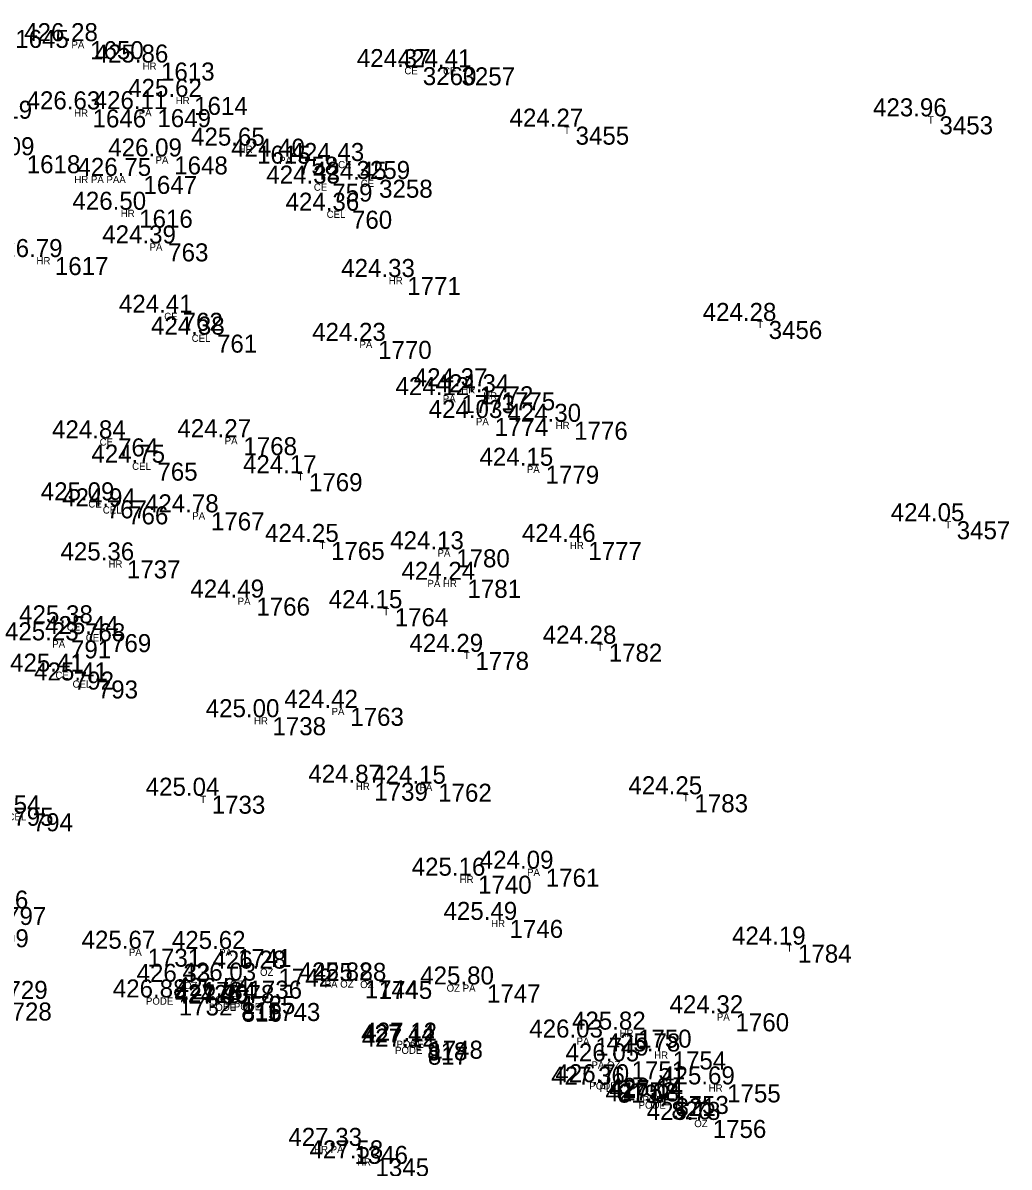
# Model space of a CAD drawing. Extents: x -639390 to -639075, y -1138747 to -1138358.
# Drawn here: x -639243.09 to -639202.03, y -1138603.62 to -1138555.98 of the extents above; entities that cross this region are included whole.
import ezdxf

# ---------------------------------------------------------------- set-up
doc = ezdxf.new("R2010")
doc.units = 0
for name, color, linetype in [('Vrstva 11', 7, 'Continuous'), ('Vrstva 12', 7, 'Continuous'), ('Vrstva 13', 7, 'Continuous'), ('Vrstva 57', 7, 'Continuous')]:
    doc.layers.add(name, color=color, linetype=linetype)

msp = doc.modelspace()

# ---------------------------------------------------------------- linework, layer by layer
at = {"layer": 'Vrstva 11'}
for p, q in [((-639240.57, -1138556.74), (-639240.57, -1138556.74)), ((-639237.62, -1138557.63), (-639237.62, -1138557.63)), ((-639226.72, -1138557.82), (-639226.72, -1138557.82)), ((-639225.11, -1138557.83), (-639225.11, -1138557.83)), ((-639236.24, -1138559.06), (-639236.24, -1138559.06)), ((-639240.47, -1138559.58), (-639240.47, -1138559.58)), ((-639237.77, -1138559.57), (-639237.77, -1138559.57)), ((-639205.21, -1138559.87), (-639205.21, -1138559.87)), ((-639220.36, -1138560.3), (-639220.36, -1138560.3)), ((-639233.62, -1138561.09), (-639233.62, -1138561.09)), ((-639237.07, -1138561.54), (-639237.07, -1138561.54)), ((-639231.92, -1138561.55), (-639231.92, -1138561.55)), ((-639229.48, -1138561.73), (-639229.48, -1138561.73)), ((-639238.35, -1138562.35), (-639238.35, -1138562.35)), ((-639230.49, -1138562.67), (-639230.49, -1138562.67)), ((-639228.54, -1138562.51), (-639228.54, -1138562.51)), ((-639238.53, -1138563.76), (-639238.53, -1138563.76)), ((-639229.67, -1138563.8), (-639229.67, -1138563.8)), ((-639237.32, -1138565.16), (-639237.32, -1138565.16)), ((-639242.04, -1138565.73), (-639242.04, -1138565.73)), ((-639227.37, -1138566.56), (-639227.37, -1138566.56)), ((-639236.72, -1138568.05), (-639236.72, -1138568.05)), ((-639212.32, -1138568.39), (-639212.32, -1138568.39)), ((-639235.29, -1138568.96), (-639235.29, -1138568.96)), ((-639228.58, -1138569.22), (-639228.58, -1138569.22)), ((-639224.35, -1138571.11), (-639224.35, -1138571.11)), ((-639223.44, -1138571.36), (-639223.44, -1138571.36)), ((-639225.11, -1138571.48), (-639225.11, -1138571.48)), ((-639223.73, -1138572.43), (-639223.73, -1138572.43)), ((-639220.42, -1138572.59), (-639220.42, -1138572.59)), ((-639239.41, -1138573.28), (-639239.41, -1138573.28)), ((-639234.19, -1138573.23), (-639234.19, -1138573.23)), ((-639237.77, -1138574.29), (-639237.77, -1138574.29)), ((-639231.46, -1138574.73), (-639231.46, -1138574.73)), ((-639221.61, -1138574.42), (-639221.61, -1138574.42)), ((-639239.88, -1138575.86), (-639239.88, -1138575.86)), ((-639238.99, -1138576.11), (-639238.99, -1138576.11)), ((-639235.54, -1138576.36), (-639235.54, -1138576.36)), ((-639204.49, -1138576.73), (-639204.49, -1138576.73)), ((-639230.54, -1138577.59), (-639230.54, -1138577.59)), ((-639225.33, -1138577.9), (-639225.33, -1138577.9)), ((-639219.83, -1138577.59), (-639219.83, -1138577.59)), ((-639239.04, -1138578.36), (-639239.04, -1138578.36)), ((-639224.86, -1138579.17), (-639224.86, -1138579.17)), ((-639233.65, -1138579.91), (-639233.65, -1138579.91)), ((-639227.89, -1138580.35), (-639227.89, -1138580.35)), ((-639240.78, -1138580.98), (-639240.78, -1138580.98)), ((-639241.37, -1138581.69), (-639241.37, -1138581.69)), ((-639239.7, -1138581.43), (-639239.7, -1138581.43)), ((-639218.98, -1138581.83), (-639218.98, -1138581.83)), ((-639224.53, -1138582.17), (-639224.53, -1138582.17)), ((-639241.25, -1138582.99), (-639241.25, -1138582.99)), ((-639240.25, -1138583.36), (-639240.25, -1138583.36)), ((-639229.74, -1138584.5), (-639229.74, -1138584.5)), ((-639232.98, -1138584.89), (-639232.98, -1138584.89)), ((-639228.74, -1138587.62), (-639228.74, -1138587.62)), ((-639226.08, -1138587.66), (-639226.08, -1138587.66)), ((-639235.51, -1138588.16), (-639235.51, -1138588.16)), ((-639215.41, -1138588.1), (-639215.41, -1138588.1)), ((-639242.96, -1138588.89), (-639242.96, -1138588.89)), ((-639221.6, -1138591.2), (-639221.6, -1138591.2)), ((-639224.42, -1138591.49), (-639224.42, -1138591.49)), ((-639223.11, -1138593.33), (-639223.11, -1138593.33)), ((-639238.18, -1138594.53), (-639238.18, -1138594.53)), ((-639234.42, -1138594.54), (-639234.42, -1138594.54)), ((-639211.1, -1138594.36), (-639211.1, -1138594.36)), ((-639232.73, -1138595.36), (-639232.73, -1138595.36)), ((-639235.89, -1138595.91), (-639235.89, -1138595.91)), ((-639233.98, -1138595.86), (-639233.98, -1138595.86)), ((-639229.14, -1138595.85), (-639229.14, -1138595.85)), ((-639228.56, -1138595.87), (-639228.56, -1138595.87)), ((-639224.05, -1138596.02), (-639224.05, -1138596.02)), ((-639236.88, -1138596.56), (-639236.88, -1138596.56)), ((-639234.26, -1138596.5), (-639234.26, -1138596.5)), ((-639234.28, -1138596.76), (-639234.28, -1138596.76)), ((-639234.26, -1138596.82), (-639234.26, -1138596.82)), ((-639233.22, -1138596.79), (-639233.22, -1138596.79)), ((-639213.7, -1138597.22), (-639213.7, -1138597.22)), ((-639217.76, -1138597.9), (-639217.76, -1138597.9)), ((-639226.54, -1138598.43), (-639226.54, -1138598.43)), ((-639226.45, -1138598.36), (-639226.45, -1138598.36)), ((-639219.54, -1138598.23), (-639219.54, -1138598.23)), ((-639226.51, -1138598.61), (-639226.51, -1138598.61)), ((-639216.32, -1138598.81), (-639216.32, -1138598.81)), ((-639218.03, -1138599.22), (-639218.03, -1138599.22)), ((-639218.61, -1138600.19), (-639218.61, -1138600.19)), ((-639218.42, -1138600.09), (-639218.42, -1138600.09)), ((-639214.05, -1138600.18), (-639214.05, -1138600.18)), ((-639216.37, -1138600.89), (-639216.37, -1138600.89)), ((-639216.21, -1138600.66), (-639216.21, -1138600.66)), ((-639216.2, -1138600.75), (-639216.2, -1138600.75)), ((-639214.65, -1138601.66), (-639214.65, -1138601.66)), ((-639229.57, -1138602.74), (-639229.57, -1138602.74)), ((-639228.69, -1138603.26), (-639228.69, -1138603.26))]:
    msp.add_line(p, q, dxfattribs=at)

# ---------------------------------------------------------------- texts
at = {"layer": 'Vrstva 12'}
for s, p in [('426.28 ', (-639243.039, -1138556.74)), ('425.86 ', (-639240.106, -1138557.63)), ('424.37 ', (-639229.189, -1138557.82)), ('424.41 ', (-639227.485, -1138557.83)), ('425.62 ', (-639238.709, -1138559.06)), ('426.63 ', (-639242.939, -1138559.58)), ('426.11 ', (-639240.145, -1138559.57)), ('423.96 ', (-639207.696, -1138559.87)), ('424.27 ', (-639222.829, -1138560.3)), ('425.65 ', (-639236.09, -1138561.09)), ('427.09 ', (-639245.679, -1138561.49)), ('426.09 ', (-639239.539, -1138561.54)), ('424.40 ', (-639234.419, -1138561.55)), ('424.43 ', (-639231.949, -1138561.73)), ('426.75 ', (-639240.82, -1138562.35)), ('424.45 ', (-639231.01, -1138562.51)), ('424.33 ', (-639232.959, -1138562.67)), ('426.50 ', (-639241.029, -1138563.76)), ('424.36 ', (-639232.156, -1138563.8)), ('424.39 ', (-639239.789, -1138565.16)), ('426.79 ', (-639244.509, -1138565.73)), ('424.33 ', (-639229.839, -1138566.56)), ('424.41 ', (-639239.095, -1138568.05)), ('424.28 ', (-639214.789, -1138568.39)), ('424.38 ', (-639237.759, -1138568.96)), ('424.23 ', (-639231.049, -1138569.22)), ('424.37 ', (-639226.819, -1138571.11)), ('424.12 ', (-639227.579, -1138571.48)), ('424.34 ', (-639225.909, -1138571.36)), ('424.03 ', (-639226.199, -1138572.43)), ('424.30 ', (-639222.919, -1138572.59)), ('424.84 ', (-639241.879, -1138573.28)), ('424.27 ', (-639236.659, -1138573.23)), ('424.75 ', (-639240.24, -1138574.29)), ('424.15 ', (-639224.08, -1138574.42)), ('424.17 ', (-639233.929, -1138574.73)), ('425.09 ', (-639242.349, -1138575.86)), ('424.94 ', (-639241.459, -1138576.11)), ('424.78 ', (-639238.009, -1138576.36)), ('424.05 ', (-639206.96, -1138576.73)), ('424.25 ', (-639233.01, -1138577.59)), ('424.46 ', (-639222.316, -1138577.59)), ('424.13 ', (-639227.799, -1138577.9)), ('425.36 ', (-639241.526, -1138578.36)), ('424.24 ', (-639227.329, -1138579.17)), ('424.49 ', (-639236.119, -1138579.91)), ('424.15 ', (-639230.36, -1138580.35)), ('425.38 ', (-639243.249, -1138580.98)), ('425.44 ', (-639242.169, -1138581.43)), ('425.23 ', (-639243.839, -1138581.69)), ('424.28 ', (-639221.449, -1138581.83)), ('424.29 ', (-639226.999, -1138582.17)), ('425.41 ', (-639243.625, -1138582.99)), ('425.41 ', (-639242.625, -1138583.36)), ('424.42 ', (-639232.209, -1138584.5)), ('425.00 ', (-639235.479, -1138584.89)), ('424.87 ', (-639231.209, -1138587.62)), ('424.15 ', (-639228.55, -1138587.66)), ('425.04 ', (-639237.979, -1138588.16)), ('424.25 ', (-639217.88, -1138588.1)), ('425.54 ', (-639245.429, -1138588.89)), ('424.09 ', (-639224.069, -1138591.2)), ('425.16 ', (-639226.906, -1138591.49)), ('425.49 ', (-639225.579, -1138593.33)), ('425.67 ', (-639240.649, -1138594.53)), ('425.62 ', (-639236.889, -1138594.54)), ('424.19 ', (-639213.569, -1138594.36)), ('426.28 ', (-639235.199, -1138595.36)), ('426.33 ', (-639238.359, -1138595.91)), ('426.03 ', (-639236.449, -1138595.86)), ('425.82 ', (-639231.609, -1138595.85)), ('425.88 ', (-639231.029, -1138595.87)), ('425.80 ', (-639226.549, -1138596.02)), ('426.88 ', (-639239.349, -1138596.56)), ('427.40 ', (-639236.779, -1138596.76)), ('427.30 ', (-639236.759, -1138596.82)), ('426.64 ', (-639236.729, -1138596.5)), ('426.78 ', (-639235.689, -1138596.79)), ('424.32 ', (-639216.169, -1138597.22)), ('427.12 ', (-639228.919, -1138598.36)), ('426.03 ', (-639222.009, -1138598.23)), ('425.82 ', (-639220.229, -1138597.9)), ('427.44 ', (-639229.009, -1138598.43)), ('427.12 ', (-639228.979, -1138598.61)), ('425.78 ', (-639218.789, -1138598.81)), ('426.05 ', (-639220.5, -1138599.22)), ('427.36 ', (-639221.096, -1138600.19)), ('426.70 ', (-639220.919, -1138600.09)), ('425.69 ', (-639216.519, -1138600.18)), ('426.64 ', (-639218.679, -1138600.66)), ('427.08 ', (-639218.839, -1138600.89)), ('427.14 ', (-639218.669, -1138600.75)), ('425.78 ', (-639217.119, -1138601.66)), ('427.33 ', (-639232.039, -1138602.74)), ('427.58 ', (-639231.159, -1138603.26))]:
    msp.add_text(s, height=0.75, dxfattribs=at).set_placement(p)
at = {"layer": 'Vrstva 13'}
for s, p in [(' 1645', (-639243.69, -1138557.02)), (' 1650', (-639240.57, -1138557.49)), (' 1613', (-639237.62, -1138558.38)), (' 3260', (-639226.72, -1138558.57)), (' 3257', (-639225.11, -1138558.58)), (' 1619', (-639245.22, -1138559.97)), (' 1614', (-639236.24, -1138559.81)), (' 1646', (-639240.47, -1138560.33)), (' 1649', (-639237.77, -1138560.32)), (' 3453', (-639205.21, -1138560.62)), (' 3455', (-639220.36, -1138561.05)), (' 1615', (-639233.62, -1138561.84)), (' 1618', (-639243.21, -1138562.24)), (' 1648', (-639237.07, -1138562.29)), (' 758', (-639231.92, -1138562.3)), (' 3259', (-639229.48, -1138562.48)), (' 1647', (-639238.35, -1138563.1)), (' 759', (-639230.49, -1138563.42)), (' 3258', (-639228.54, -1138563.26)), (' 1616', (-639238.53, -1138564.51)), (' 760', (-639229.67, -1138564.55)), (' 763', (-639237.32, -1138565.91)), (' 1617', (-639242.04, -1138566.48)), (' 1771', (-639227.37, -1138567.31)), (' 762', (-639236.72, -1138568.8)), (' 3456', (-639212.32, -1138569.14)), (' 761', (-639235.29, -1138569.71)), (' 1770', (-639228.58, -1138569.97)), (' 1772', (-639224.35, -1138571.86)), (' 1775', (-639223.44, -1138572.11)), (' 1773', (-639225.11, -1138572.23)), (' 1774', (-639223.73, -1138573.18)), (' 1776', (-639220.42, -1138573.34)), (' 764', (-639239.41, -1138574.03)), (' 1768', (-639234.19, -1138573.98)), (' 765', (-639237.77, -1138575.04)), (' 1769', (-639231.46, -1138575.48)), (' 1779', (-639221.61, -1138575.17)), (' 767', (-639239.88, -1138576.61)), (' 766', (-639238.99, -1138576.86)), (' 1767', (-639235.54, -1138577.11)), (' 3457', (-639204.49, -1138577.48)), (' 1765', (-639230.54, -1138578.34)), (' 1780', (-639225.33, -1138578.65)), (' 1777', (-639219.83, -1138578.34)), (' 1737', (-639239.04, -1138579.11)), (' 1781', (-639224.86, -1138579.92)), (' 1766', (-639233.65, -1138580.66)), (' 1764', (-639227.89, -1138581.1)), (' 768', (-639240.78, -1138581.73)), (' 791', (-639241.37, -1138582.44)), (' 769', (-639239.7, -1138582.18)), (' 1782', (-639218.98, -1138582.58)), (' 1778', (-639224.53, -1138582.92)), (' 792', (-639241.25, -1138583.74)), (' 793', (-639240.25, -1138584.11)), (' 1763', (-639229.74, -1138585.25)), (' 1738', (-639232.98, -1138585.64)), (' 1739', (-639228.74, -1138588.37)), (' 1762', (-639226.08, -1138588.41)), (' 1733', (-639235.51, -1138588.91)), (' 1783', (-639215.41, -1138588.85)), (' 795', (-639243.77, -1138589.41)), (' 794', (-639242.96, -1138589.64)), (' 1761', (-639221.6, -1138591.95)), (' 1740', (-639224.42, -1138592.24)), (' 796', (-639244.82, -1138592.86)), (' 797', (-639244.07, -1138593.54)), (' 809', (-639244.8, -1138594.47)), (' 1746', (-639223.11, -1138594.08)), (' 1731', (-639238.18, -1138595.28)), (' 1741', (-639234.42, -1138595.29)), (' 1784', (-639211.1, -1138595.11)), (' 1742', (-639232.73, -1138596.11)), (' 1729', (-639244.57, -1138596.62)), (' 1734', (-639235.89, -1138596.66)), (' 1736', (-639233.98, -1138596.61)), (' 1744', (-639229.14, -1138596.6)), (' 1745', (-639228.56, -1138596.62)), (' 1747', (-639224.05, -1138596.77)), (' 1732', (-639236.88, -1138597.31)), (' 1735', (-639234.26, -1138597.25)), (' 1728', (-639244.4, -1138597.52)), (' 815', (-639234.28, -1138597.51)), (' 816', (-639234.26, -1138597.57)), (' 1743', (-639233.22, -1138597.54)), (' 1760', (-639213.7, -1138597.97)), (' 1750', (-639217.76, -1138598.65)), (' 818', (-639226.54, -1138599.18)), (' 1748', (-639226.45, -1138599.11)), (' 1749', (-639219.54, -1138598.98)), (' 817', (-639226.51, -1138599.36)), (' 1754', (-639216.32, -1138599.56)), (' 1751', (-639218.03, -1138599.97)), (' 819', (-639218.61, -1138600.94)), (' 1752', (-639218.42, -1138600.84)), (' 1755', (-639214.05, -1138600.93)), (' 820', (-639216.37, -1138601.64)), (' 821', (-639216.2, -1138601.5)), (' 1753', (-639216.21, -1138601.41)), (' 1756', (-639214.65, -1138602.41)), (' 1346', (-639229.57, -1138603.49)), (' 1345', (-639228.69, -1138604.01))]:
    msp.add_text(s, height=0.75, dxfattribs=at).set_placement(p)
at = {"layer": 'Vrstva 57'}
for s, p in [('PA', (-639241.07, -1138557.04)), ('HR', (-639238.109, -1138557.93)), ('CE', (-639227.208, -1138558.12)), ('CE', (-639225.598, -1138558.13)), ('HR', (-639236.729, -1138559.36)), ('HR', (-639240.959, -1138559.88)), ('PA', (-639238.27, -1138559.87)), ('T', (-639205.41, -1138560.17)), ('T', (-639220.56, -1138560.6)), ('HR', (-639234.109, -1138561.39)), ('PA', (-639237.57, -1138561.84)), ('PA', (-639232.42, -1138561.85)), ('CE', (-639229.968, -1138562.03)), ('HR PA PAA', (-639240.95, -1138562.65)), ('CE', (-639230.978, -1138562.97)), ('CE', (-639229.027, -1138562.81)), ('HR', (-639239.019, -1138564.06)), ('CEL', (-639230.445, -1138564.1)), ('PA', (-639237.82, -1138565.46)), ('HR', (-639242.529, -1138566.03)), ('HR', (-639227.859, -1138566.86)), ('CE', (-639237.208, -1138568.35)), ('T', (-639212.52, -1138568.69)), ('CEL', (-639236.065, -1138569.26)), ('PA', (-639229.08, -1138569.52)), ('HR', (-639224.839, -1138571.41)), ('HR', (-639223.929, -1138571.66)), ('PA', (-639225.61, -1138571.78)), ('PA', (-639224.23, -1138572.73)), ('HR', (-639220.909, -1138572.89)), ('CE', (-639239.897, -1138573.58)), ('PA', (-639234.69, -1138573.53)), ('CEL', (-639238.545, -1138574.59)), ('T', (-639231.66, -1138575.03)), ('PA', (-639222.11, -1138574.72)), ('CE', (-639240.368, -1138576.16)), ('CEL', (-639239.765, -1138576.41)), ('PA', (-639236.04, -1138576.66)), ('T', (-639204.69, -1138577.03)), ('T', (-639230.74, -1138577.89)), ('PA', (-639225.83, -1138578.2)), ('HR', (-639220.319, -1138577.89)), ('HR', (-639239.529, -1138578.66)), ('PA HR', (-639226.249, -1138579.47)), ('PA', (-639234.15, -1138580.21)), ('T', (-639228.09, -1138580.65)), ('CE', (-639241.267, -1138581.28)), ('PA', (-639241.87, -1138581.99)), ('CEL', (-639240.475, -1138581.73)), ('T', (-639219.18, -1138582.13)), ('T', (-639224.73, -1138582.47)), ('CE', (-639241.738, -1138583.29)), ('CEL', (-639241.025, -1138583.66)), ('PA', (-639230.24, -1138584.8)), ('HR', (-639233.469, -1138585.19)), ('HR', (-639229.229, -1138587.92)), ('PA', (-639226.58, -1138587.96)), ('T', (-639235.71, -1138588.46)), ('T', (-639215.61, -1138588.4)), ('CEL', (-639243.735, -1138589.19)), ('PA', (-639222.1, -1138591.5)), ('HR', (-639224.909, -1138591.79)), ('HR', (-639223.599, -1138593.63)), ('PA', (-639238.68, -1138594.83)), ('PA', (-639234.92, -1138594.84)), ('T', (-639211.3, -1138594.66)), ('OZ', (-639233.219, -1138595.66)), ('OZ', (-639236.379, -1138596.21)), ('OZ', (-639234.469, -1138596.16)), ('PA OZ', (-639230.529, -1138596.15)), ('OZ', (-639229.049, -1138596.17)), ('OZ PA', (-639225.45, -1138596.32)), ('PODE', (-639237.968, -1138596.86)), ('PODE', (-639235.348, -1138596.8)), ('PODE', (-639235.348, -1138597.12)), ('PL', (-639234.755, -1138597.06)), ('PODE', (-639234.307, -1138597.09)), ('PA', (-639214.2, -1138597.52)), ('HR', (-639218.249, -1138598.2)), ('PODE', (-639227.537, -1138598.66)), ('PL', (-639227.015, -1138598.73)), ('PA', (-639220.04, -1138598.53)), ('PODE', (-639227.598, -1138598.91)), ('HR', (-639216.809, -1138599.11)), ('PA OZ', (-639219.419, -1138599.52)), ('PODE', (-639219.508, -1138600.39)), ('PL', (-639219.085, -1138600.49)), ('HR', (-639214.539, -1138600.48)), ('PODE', (-639217.458, -1138601.19)), ('PODE', (-639217.297, -1138600.96)), ('PL', (-639216.675, -1138601.05)), ('OZ', (-639215.139, -1138601.96)), ('HR PA', (-639230.97, -1138603.04)), ('HR', (-639229.179, -1138603.56))]:
    msp.add_text(s, height=0.3, dxfattribs=at).set_placement(p)

doc.saveas('drawing.dxf')
